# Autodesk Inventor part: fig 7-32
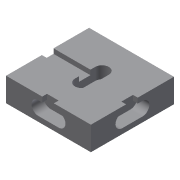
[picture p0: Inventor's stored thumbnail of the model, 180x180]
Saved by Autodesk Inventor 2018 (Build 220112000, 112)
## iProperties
Created: 2004-05
Part Number: fig 7-32
Document SubType Name: Modeling
Designer: CADCIM Technologies
Manufacturer: Standard
Standards Organization: Custom
Density: 1 g/cm^3
Material: Generic
Appearance: Default
Author: CADCIM Technologies
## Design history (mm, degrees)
sketch "Sketch1"
  geometry: L1 (-30.233, -25.517)-(22.302, -25.517); L2 (22.302, -25.517)-(22.302, 25.904); L3 (22.302, 25.904)-(-30.233, 25.904); L4 (-30.233, 25.904)-(-30.233, -25.517)
  constraints: 8 end point, 2 parallel, 1 horizontal, 1 perpendicular
extrude "Extrusion1" new body sketch "Sketch1" distance "d0" = 14.75; taper "d1" = 0 deg
sketch "Sketch2"
  geometry: L1 (1.047, -5.75)-(1.047, 6.846); L2 (-7.35, 6.845)-(-7.35, -5.75); A1 r 4.198 centre (-3.152, 6.846) between (1.047, 6.846) and (-7.35, 6.845); A2 r 4.198 centre (-3.152, -5.75) between (-7.35, -5.75) and (1.047, -5.75)
  constraints: 4 end point, 4 point on circle, 4 tangent, 2 centre point, 1 parallel
extrude "Extrusion2" cut sketch "Sketch2" distance "d2" = 7.5; taper "d3" = 0 deg
sketch "Sketch3"
  geometry: L1 (-7.5, 0)-(-7.5, 12.595) reference; L2 (-7.5, 0)-(0, 0) reference; L3 (-7.5, 2.416)-(-4.537, 2.416); L4 (-4.537, 2.416)-(-4.537, 9.616); L5 (-4.537, 9.616)-(-7.5, 9.616)
  constraints: 6 end point, 2 perpendicular, 2 point on line, 1 parallel
extrude "Extrusion3" cut sketch "Sketch3" extent not by distance; stored distance "d4" = 6.75; taper "d5" = 0 deg
sketch "Sketch4"
  geometry: L1 (1.047, -5.75)-(1.047, 6.846); L2 (-7.35, 6.845)-(-7.35, -5.75); A1 r 4.198 centre (-3.152, 6.846) between (1.047, 6.846) and (-7.35, 6.845); A2 r 4.198 centre (-3.152, -5.75) between (-7.35, -5.75) and (1.047, -5.75)
  constraints: 4 end point, 4 point on circle, 4 tangent, 2 centre point, 1 parallel
extrude "Extrusion4" cut sketch "Sketch4" taper "d7" = 0 deg; distance "d8" = 7.5
sketch "Sketch5"
  geometry: L1 (-7.5, 0)-(-7.5, 12.595) reference; L2 (-7.5, 0)-(0, 0) reference; L3 (-7.5, 2.416)-(-4.537, 2.416); L4 (-4.537, 2.416)-(-4.537, 9.616); L5 (-4.537, 9.616)-(-7.5, 9.616)
  constraints: 6 end point, 2 perpendicular, 2 point on line, 1 parallel
extrude "Extrusion5" cut sketch "Sketch5" extent not by distance; taper "d10" = 0 deg; stored distance "d11" = 6.75
sketch "Sketch6"
  geometry: L1 (1.047, -5.75)-(1.047, 6.846); L2 (-7.35, 6.845)-(-7.35, -5.75); A1 r 4.198 centre (-3.152, 6.846) between (1.047, 6.846) and (-7.35, 6.845); A2 r 4.198 centre (-3.152, -5.75) between (-7.35, -5.75) and (1.047, -5.75)
  constraints: 4 end point, 4 point on circle, 4 tangent, 2 centre point, 1 parallel
extrude "Extrusion6" cut sketch "Sketch6" taper "d13" = 0 deg; distance "d14" = 7.5
sketch "Sketch7"
  geometry: L1 (-7.5, 0)-(-7.5, 12.595) reference; L2 (-7.5, 0)-(0, 0) reference; L3 (-7.5, 2.416)-(-4.537, 2.416); L4 (-4.537, 2.416)-(-4.537, 9.616); L5 (-4.537, 9.616)-(-7.5, 9.616)
  constraints: 6 end point, 2 perpendicular, 2 point on line, 1 parallel
extrude "Extrusion7" cut sketch "Sketch7" extent not by distance; taper "d16" = 0 deg; stored distance "d17" = 6.75
body "Solid1"
